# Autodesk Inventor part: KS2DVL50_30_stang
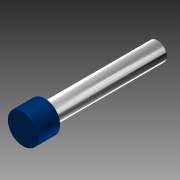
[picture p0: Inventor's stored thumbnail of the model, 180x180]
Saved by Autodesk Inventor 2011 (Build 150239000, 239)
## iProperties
Created: 2010-11
Document SubType Name: Modeling
Designer: TB
Mass: 161.233 g
Surface Area: 236.814 cm^2
Volume: 161.233 cm^3
Density: 1 g/cm^3
Author: TB
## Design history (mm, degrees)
sketch "Sketch2"
  geometry: L1 (-35, -3)-(-35, 3) reference; L2 (-35, -9)-(-35, 9) reference; L3 (-35, 15)-(-253, 15); L4 (-253, 15)-(-253, 0); L5 (-253, 0)-(-35, 0); L6 (-35, 0)-(-35, 15); L7 (-253, 15)-(-216, 15); L8 (-216, 15)-(-216, 25); L9 (-216, 25)-(-253, 25); L10 (-253, 25)-(-253, 15); 1 further point
  constraints: 16 end point, 4 parallel, 2 horizontal, 2 perpendicular, 1 midpoint
  dimensions: "Dia" = 30 diameter of L3 L5; "d3" = 218 distance of L3.start L3.end (computed from Slaglengde, Forlengelse_rør); "StempelDia" = 50 diameter of L9 L5; "StempelLengde" = 37 distance of L8.end L9.end
revolve "Revolution1" sketch "Sketch2" stored, may be unused: angle "d6" = 90 deg
fillet "Fillet1" dims "d7" = 2
sketch "Sketch3"
  geometry: L1 (-253, -23)-(-253, 23) reference; L2 (-253, 0)-(-253.01, 0); L3 (-253, 0)-(-253, 0.01); A1 r 0.01 centre (-253, 0) between (-253, 0.01) and (-253.01, 0); 1 further point
  constraints: 4 end point, 2 point on circle, 1 centre point, 1 midpoint, 1 perpendicular, 1 point on line
  dimensions: "d8" = 0.01 distance of L2.start L2.end; "d9" = 0.01 distance of L2.start L3.end (= d8); "d10" = 0.01 radius of A1 (= d8)
revolve "Revolution2" sketch "Sketch3" stored, may be unused: angle "d11" = 90 deg
body "Solid1"
node "Projected Loop2"
other parameters: "Forlengelse_rør" = 0
